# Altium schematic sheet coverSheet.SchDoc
size 431 x 279 mm; Date: Not shown in title block; ApprovedBy: Not shown in title block; CheckedBy: Not shown in title block; Author: Not shown in title block; CompanyName: Not shown in title block; Engineer: Not shown in title block; Organization: Not shown in title block; Address1: Not shown in title block; Address2: Not shown in title block; Address3: Not shown in title block; Address4: Not shown in title block; DocumentNumber: 1; Revision: Use project parameter SCH_Rev; SheetNumber: 1; SheetTotal: 3; PageSetup: Record=PageOptions¦CenterHorizontal=True¦CenterVertical=True¦PrintScale=1.00¦XCorrection=1.00¦YCorrection=1.00¦PrintKind=0¦BorderSize=5000000¦LeftOffset=0¦BottomOffset=0¦Orientation=2¦PaperLength=1000¦PaperWidth=1000¦Scale=100¦PaperSource=15¦PrintQuality=600¦MediaType=1¦DitherType=10¦PaperKind=Letter¦PrintScaleMode=1
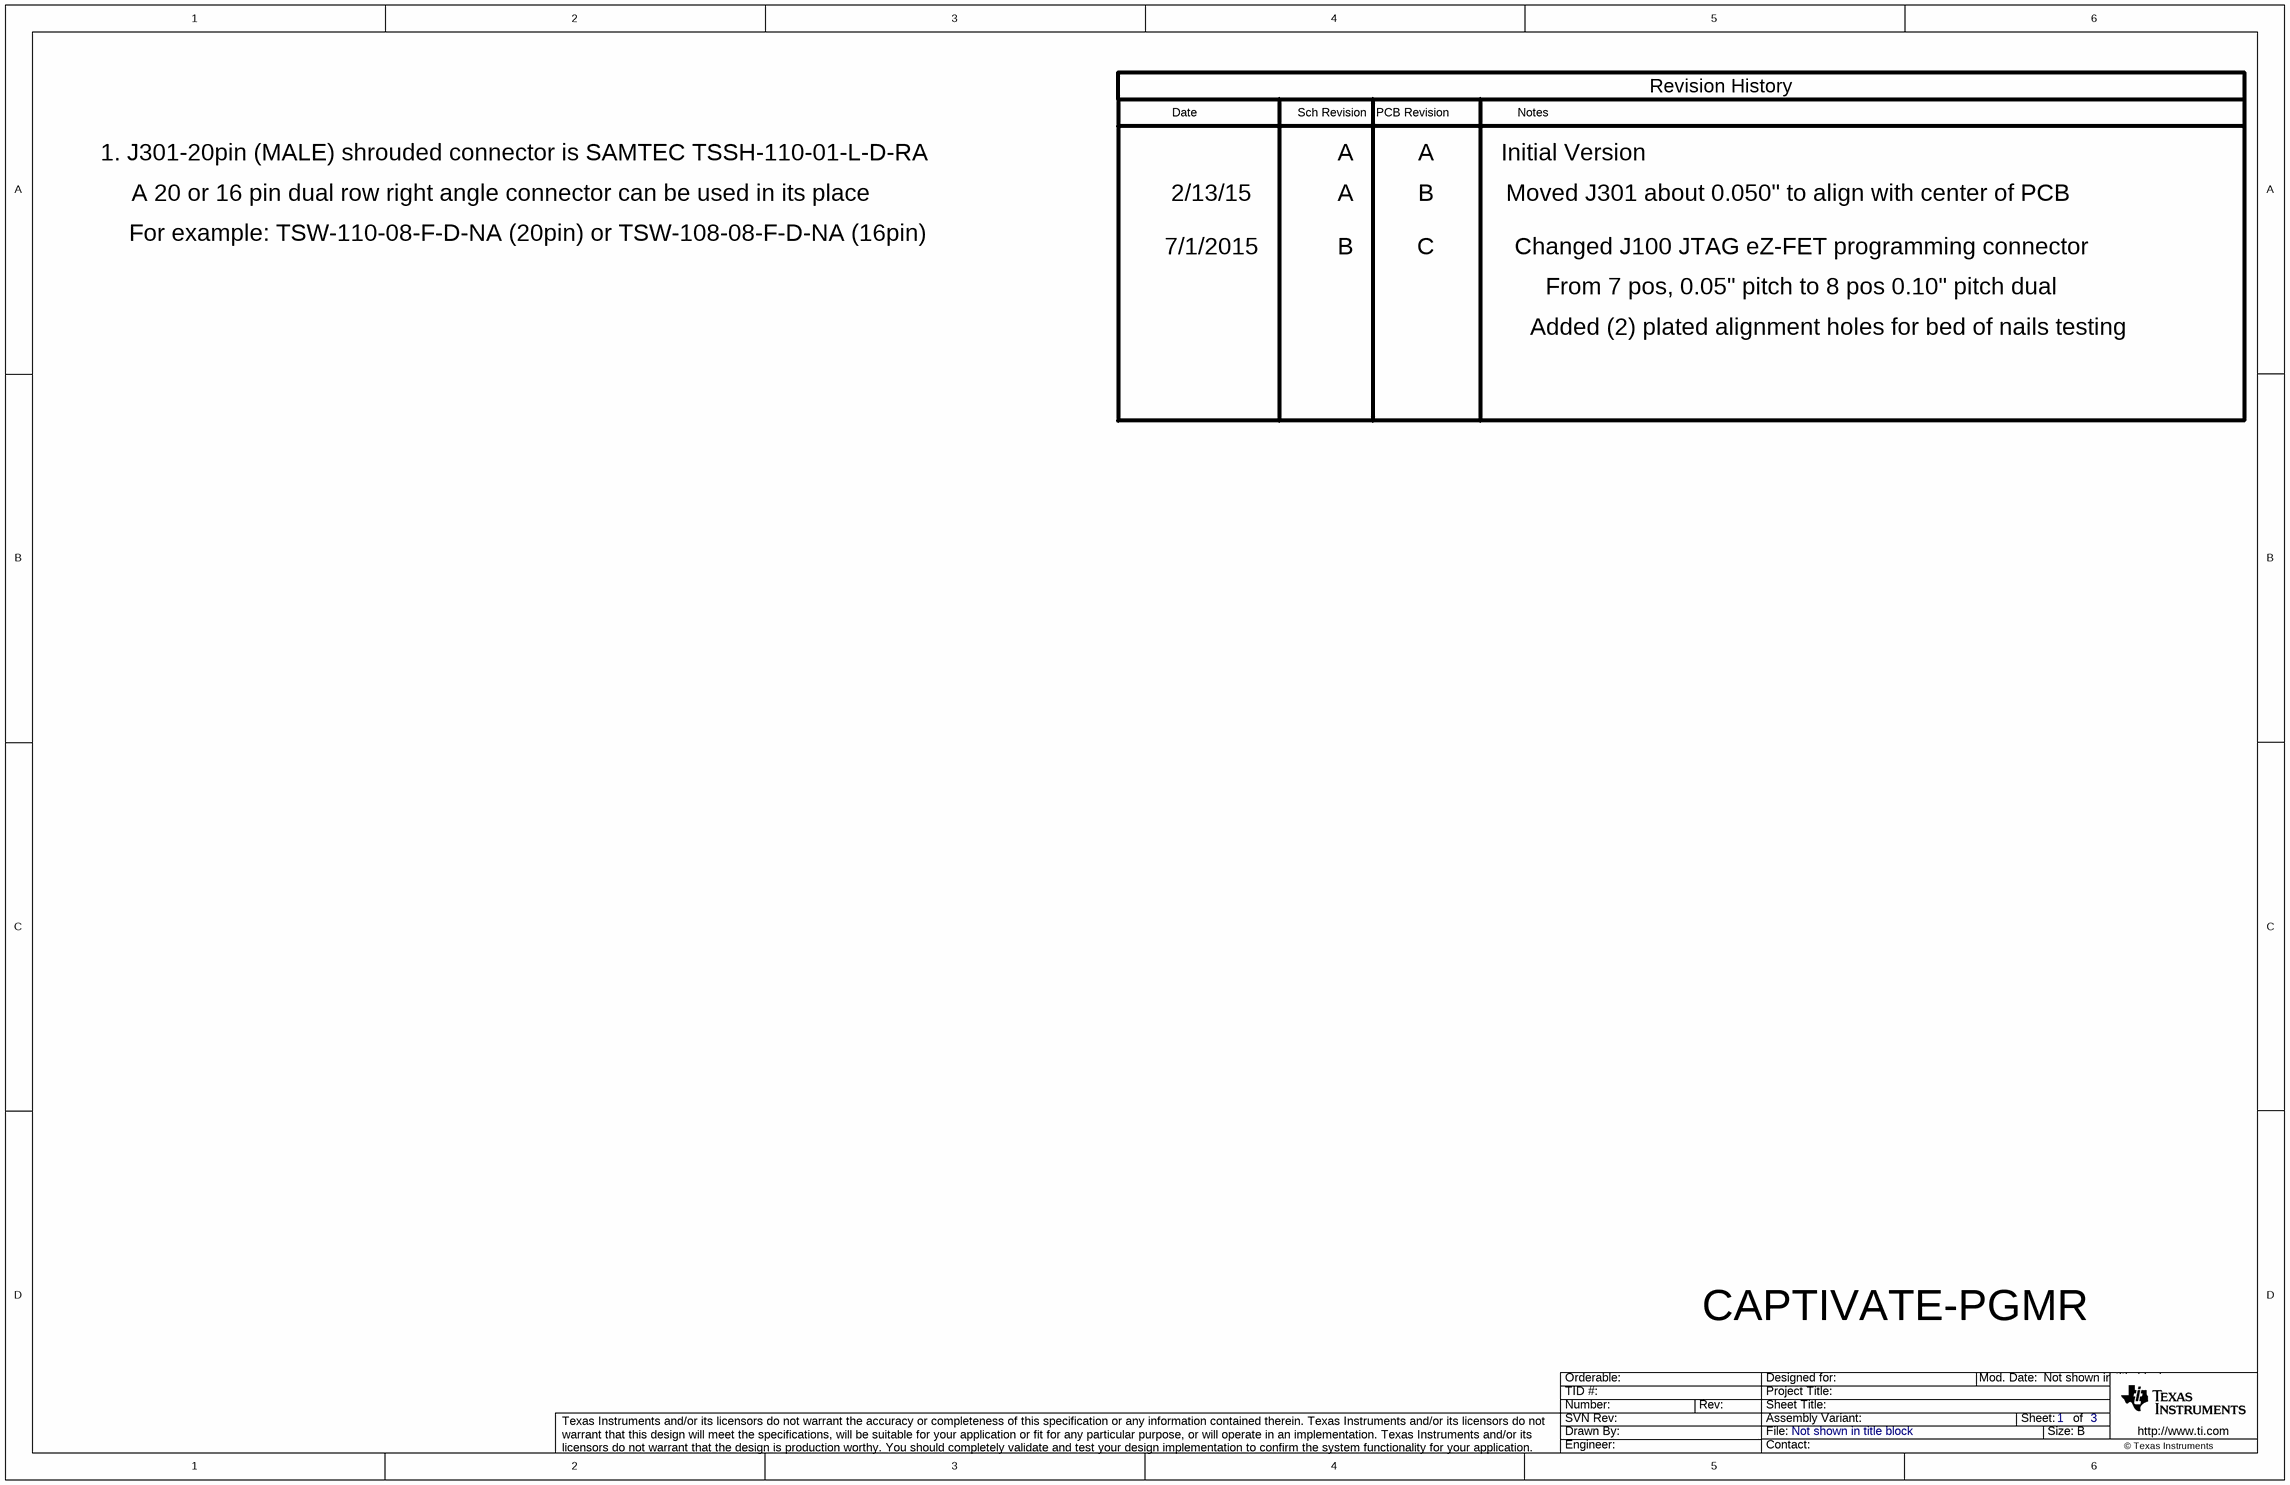
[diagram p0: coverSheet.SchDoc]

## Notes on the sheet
- Revision History
- 1. J301-20pin (MALE) shrouded connector is SAMTEC TSSH-110-01-L-D-RA
- Date
- Sch Revision
- A
- PCB Revision
- Notes
- Initial Version
- A 20 or 16 pin dual row right angle connector can be used in its place
- For example: TSW-110-08-F-D-NA (20pin) or TSW-108-08-F-D-NA (16pin)
- 2/13/15
- B
- Moved J301 about 0.050" to align with center of PCB
- 7/1/2015
- C
- Changed J100 JTAG eZ-FET programming connector
- From 7 pos, 0.05" pitch to 8 pos 0.10" pitch dual
- Added (2) plated alignment holes for bed of nails testing
- CAPTIVATE-PGMR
